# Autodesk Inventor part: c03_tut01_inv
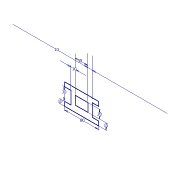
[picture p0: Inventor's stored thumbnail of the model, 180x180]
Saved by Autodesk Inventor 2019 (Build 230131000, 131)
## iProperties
Created: 2017-04
Part Number: c03_tut01_inv
Material: Generic
Document SubType Name: Modeling
Designer: CADCIM 00
Density: 1 g/cm^3
Appearance: Default
Author: CADCIM 00
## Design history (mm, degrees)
sketch "Sketch1"
  geometry: 1 further point
sketch "Sketch2"
  geometry: L1 (0, 0)-(0, 10); L2 (0, 10)-(-15, 10); L3 (-15, 10)-(-15, 40); L4 (-15, 40)-(0, 40); L5 (0, 40)-(0, 50); L6 (0, 50)-(-80, 50); L7 (-80, 50)-(-80, 40); L8 (-80, 40)-(-65, 40); L9 (-65, 40)-(-65, 10); L10 (-65, 10)-(-80, 10); L11 (-80, 0)-(0, 0); L12 (-80, 10)-(-80, 0); L13 (-25, 35)-(-55, 35); L14 (-55, 35)-(-55, 15); L15 (-55, 15)-(-25, 15); L16 (-25, 15)-(-25, 35)
  constraints: 32 end point, 8 perpendicular, 8 point on line, 3 parallel, 2 collinear, 1 horizontal, 1 vertical
  dimensions: "d0" = 80 distance of L11.start L1.start; "d1" = 10 distance of L1.start L1.end; "d2" = 30 distance of L2.end L3.end; "d3" = 10 distance between parallel lines of L16 L3; "d4" = 10 distance between parallel lines of L9 L14; "d5" = 15 distance between parallel lines of L15 L11; "d6" = 20 distance of L13.end L14.end; "d7" = 30 distance of L13.start L13.end
